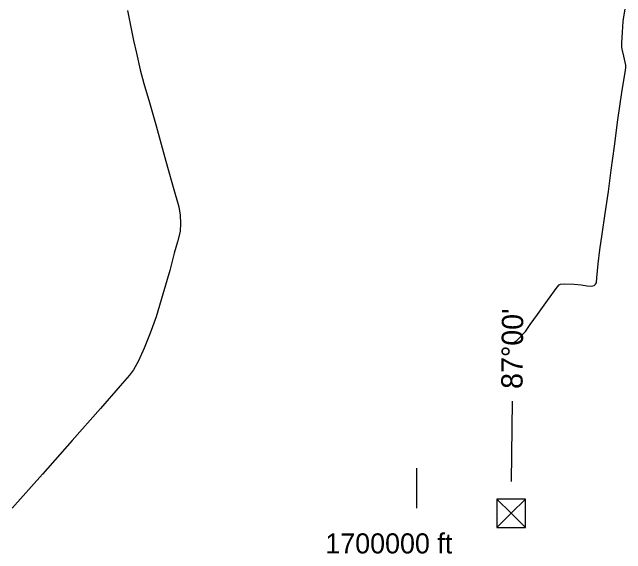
# Model space of a CAD drawing. Extents: x 1551132 to 1791609, y 378168 to 563823.
# Drawn here: x 1660449 to 1672664, y 379893 to 390671 of the extents above; entities that cross this region are included whole.
import ezdxf

# ---------------------------------------------------------------- set-up
doc = ezdxf.new("R2010")
doc.units = 0
for name, color, linetype in [('DESIGN - TRAFFIC CONTROL PERMANENT - Pavement Marking', 7, 'Continuous'), ('SURVEY - CENTERLINE - Preliminary Text', 7, 'Continuous'), ('SURVEY - CONTOURS - Index with Text', 7, 'Continuous'), ('SURVEY - DRAINAGE - Bridge Hydraulic Data - Points - Locators', 7, 'Continuous'), ('SURVEY - NON-TRANSPORTATION - Features - Points - Locators', 7, 'Continuous')]:
    doc.layers.add(name, color=color, linetype=linetype)

msp = doc.modelspace()

# ---------------------------------------------------------------- linework, layer by layer
at = {"layer": 'DESIGN - TRAFFIC CONTROL PERMANENT - Pavement Marking'}
for p, q in [((1670665.386, 380980.711), (1670099.684, 380980.697)), ((1670382.542, 380697.854), (1670099.684, 380980.697)), ((1670099.684, 380980.697), (1670099.699, 380414.996)), ((1670382.542, 380697.854), (1670665.386, 380980.711)), ((1670665.4, 380415.01), (1670665.386, 380980.711)), ((1670099.699, 380414.996), (1670382.542, 380697.854)), ((1670382.542, 380697.854), (1670665.4, 380415.01)), ((1670099.699, 380414.996), (1670665.4, 380415.01))]:
    msp.add_line(p, q, dxfattribs=at)
at = {"layer": 'SURVEY - CENTERLINE - Preliminary Text'}
msp.add_lwpolyline([(1662742.209, 390709.423), (1662862.948, 390112.057), (1662921.571, 389859.442), (1662995.761, 389526.642), (1663068.284, 389253.918), (1663178.248, 388876.866), (1663311.745, 388413.587), (1663433.375, 387974.401), (1663539.28, 387587.366), (1663651.128, 387190.28), (1663763.033, 386801.212), (1663794.099, 386630.84), (1663799.174, 386464.611), (1663794.282, 386306.457), (1663739.1, 386102.518), (1663671.785, 385874.629), (1663583.787, 385528.711), (1663449.056, 385056.899), (1663312.443, 384607.128), (1663196.545, 384281.386), (1663074.814, 383987.72), (1662965.325, 383734.022), (1662864.261, 383556.375), (1662783.604, 383448.697), (1662600.283, 383235.458), (1662203.484, 382783.121), (1661639.555, 382149.496), (1661049.377, 381475.969), (1660449.174, 380796.493)], dxfattribs=at)
at = {"layer": 'SURVEY - CONTOURS - Index with Text'}
msp.add_lwpolyline([(1670430.601, 384100.652), (1670488.35, 384132.786), (1670550.54, 384192.688), (1670602.714, 384248.606), (1670664.929, 384318.508), (1670761.318, 384458.378), (1670903.882, 384656.192), (1671104.669, 384935.916), (1671299.431, 385201.657), (1671341.564, 385245.591), (1671363.63, 385261.55), (1671443.736, 385267.367), (1671637.965, 385258.925), (1671774.112, 385248.608), (1671898.217, 385226.316), (1671990.323, 385218.099), (1672036.406, 385231.999), (1672064.488, 385255.958), (1672078.563, 385285.942), (1672090.771, 385387.978), (1672115.346, 385666.111), (1672149.92, 385942.218), (1672194.586, 386256.318), (1672253.46, 386666.462), (1672320.383, 387100.599), (1672375.282, 387526.752), (1672442.289, 388004.915), (1672507.396, 388533.12), (1672586.536, 389071.293), (1672659.493, 389517.43), (1672663.593, 389565.448), (1672663.702, 389621.482), (1672649.794, 389679.559), (1672627.994, 389795.679), (1672592.228, 389939.857), (1672588.312, 389985.9), (1672588.454, 390057.944), (1672600.887, 390272.058), (1672613.328, 390490.172), (1672627.52, 390582.199), (1672653.844, 390732.245)], dxfattribs=at)
at = {"layer": 'SURVEY - DRAINAGE - Bridge Hydraulic Data - Points - Locators'}
msp.add_line((1670391.792, 381330.254), (1670408.134, 382930.213), dxfattribs=at)
at = {"layer": 'SURVEY - NON-TRANSPORTATION - Features - Points - Locators'}
msp.add_line((1668506.936, 380798.305), (1668506.936, 381598.326), dxfattribs=at)

# ---------------------------------------------------------------- texts
at = {"layer": 'SURVEY - DRAINAGE - Bridge Hydraulic Data - Points - Locators'}
msp.add_text("87°00'", height=425.0112, rotation=89.4145611, dxfattribs=at).set_placement((1670608.215, 383171.936))
at = {"layer": 'SURVEY - NON-TRANSPORTATION - Features - Points - Locators'}
msp.add_text('1700000 ft', height=399.9823, rotation=0.0000306, dxfattribs=at).set_placement((1666682.02, 379898.317))

doc.saveas('drawing.dxf')
